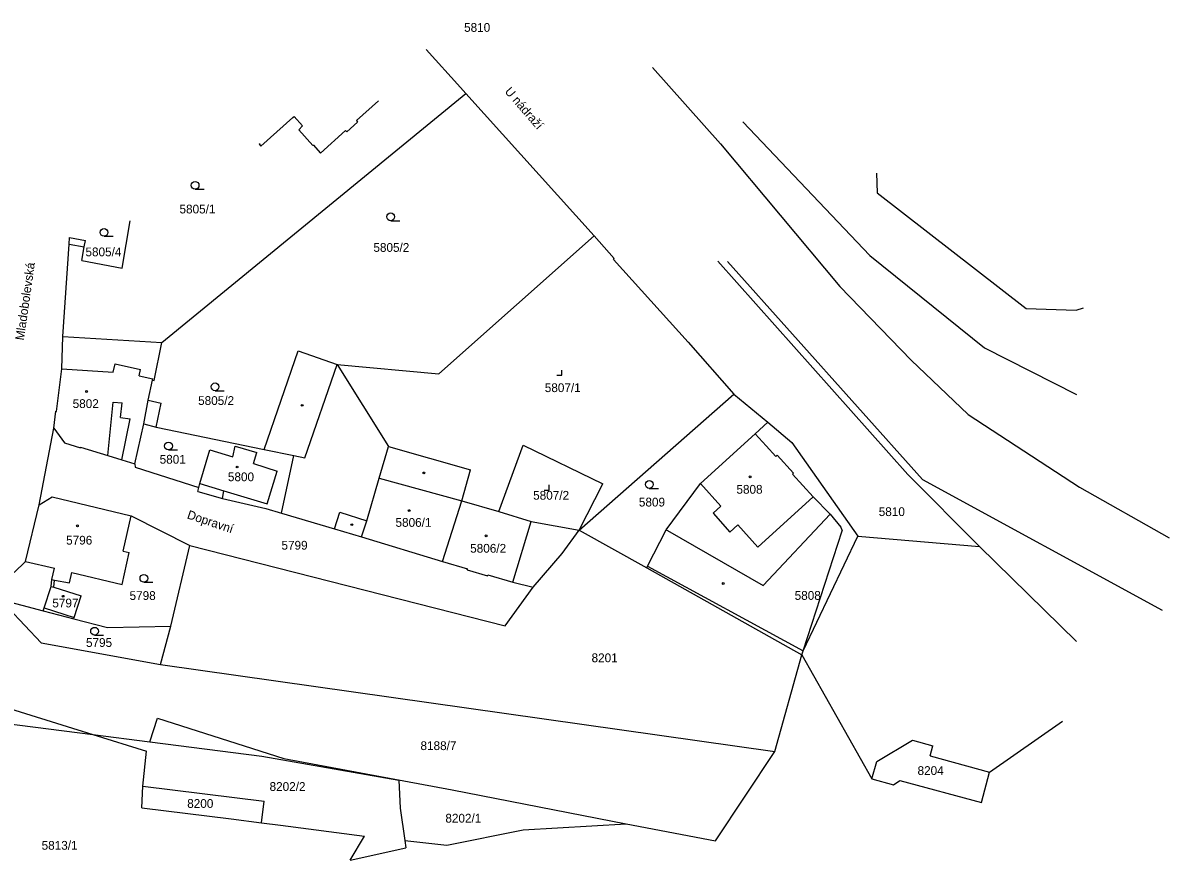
# Model space of a CAD drawing. Extents: x -717507 to -715515, y -957700 to -954941.
# Drawn here: x -715773.2 to -715551.5, y -955101.9 to -954940.9 of the extents above; entities that cross this region are included whole.
import ezdxf

# ---------------------------------------------------------------- set-up
doc = ezdxf.new("R2010")
doc.units = 0
for name, color, linetype in [('Hranice parcel', 7, 'Continuous'), ('Parcelní čísla', 7, 'Continuous'), ('Pop  PČ popisy', 7, 'Continuous'), ('Vnitřní kresba', 7, 'Continuous'), ('Značky budov', 7, 'Continuous'), ('Značky kultur', 7, 'Continuous')]:
    doc.layers.add(name, color=color, linetype=linetype)

msp = doc.modelspace()

# ---------------------------------------------------------------- linework, layer by layer
at = {"layer": 'Hranice parcel'}
for points in [[(-715695.18, -954946.06), (-715688.55, -954953.42)], [(-715651.42, -954949.56), (-715638.23, -954964.35)], [(-715688.55, -954953.42), (-715687.49, -954954.6)], [(-715746.28, -955002.75), (-715687.49, -954954.6)], [(-715708.67, -954959.84), (-715704.37, -954955.99)], [(-715687.49, -954954.6), (-715662.66, -954982.12)], [(-715727.15, -954964.76), (-715720.95, -954959.22)], [(-715720.95, -954959.22), (-715720.72, -954959.01)], [(-715720.72, -954959.01), (-715719.08, -954960.85)], [(-715710.55, -954962), (-715708.44, -954960.11)], [(-715708.67, -954959.84), (-715708.44, -954960.11)], [(-715633.96, -954960.07), (-715609.35, -954985.91)], [(-715719.82, -954961.59), (-715719.08, -954960.85)], [(-715719.82, -954961.59), (-715717.12, -954964.65)], [(-715715.65, -954966.1), (-715710.79, -954961.74)], [(-715710.79, -954961.74), (-715710.55, -954962)], [(-715727.46, -954964.41), (-715727.31, -954964.28)], [(-715727.46, -954964.41), (-715727.15, -954964.76)], [(-715717.12, -954964.65), (-715717.01, -954964.55)], [(-715717.01, -954964.55), (-715715.65, -954966.1)], [(-715638.23, -954964.35), (-715615.16, -954991.91)], [(-715608.08, -954970), (-715607.94, -954973.8)], [(-715607.94, -954973.8), (-715579.15, -954996.19)], [(-715754.01, -954988.4), (-715752.42, -954979.21)], [(-715764.23, -954983.73), (-715764.14, -954982.46)], [(-715764.14, -954982.46), (-715761.09, -954983.03)], [(-715692.71, -955008.8), (-715662.66, -954982.12)], [(-715662.66, -954982.12), (-715658.79, -954986.51)], [(-715765.46, -955001.59), (-715764.23, -954983.73)], [(-715764.23, -954983.73), (-715761.33, -954984.27)], [(-715761.81, -954986.87), (-715761.33, -954984.27)], [(-715761.81, -954986.87), (-715754.01, -954988.4)], [(-715658.94, -954986.68), (-715658.79, -954986.51)], [(-715658.94, -954986.68), (-715644.51, -955002.69)], [(-715638.8, -954987), (-715602, -955028.3)], [(-715636.93, -954987.11), (-715599.17, -955029.27)], [(-715609.35, -954985.91), (-715587.16, -955003.81)], [(-715615.16, -954991.91), (-715601.39, -955006.15)], [(-715579.15, -954996.19), (-715569.45, -954996.5)], [(-715569.45, -954996.5), (-715568.03, -954996.04)], [(-715765.67, -955007.85), (-715765.46, -955001.59)], [(-715765.46, -955001.59), (-715746.28, -955002.75)], [(-715747.81, -955010.09), (-715746.28, -955002.75)], [(-715726.53, -955023.47), (-715719.91, -955004.38)], [(-715719.91, -955004.38), (-715712.38, -955006.99)], [(-715644.51, -955002.69), (-715635.66, -955012.72)], [(-715587.16, -955003.81), (-715569.37, -955012.8)], [(-715712.38, -955006.99), (-715692.71, -955008.8)], [(-715712.38, -955006.99), (-715702.48, -955022.9)], [(-715601.39, -955006.15), (-715590.37, -955016.71)], [(-715766.67, -955016.08), (-715765.67, -955007.85)], [(-715748.97, -955013.91), (-715748.09, -955010.03)], [(-715748.09, -955010.03), (-715747.81, -955010.09)], [(-715665.6, -955039.04), (-715635.66, -955012.72)], [(-715635.66, -955012.72), (-715629.09, -955018.19)], [(-715749.79, -955018.5), (-715748.97, -955013.91)], [(-715767.18, -955019.31), (-715766.78, -955016.07)], [(-715766.78, -955016.07), (-715766.67, -955016.08)], [(-715631.54, -955020.41), (-715629.09, -955018.19)], [(-715629.09, -955018.19), (-715624.43, -955022.07)], [(-715590.37, -955016.71), (-715568.8, -955030.77)], [(-715770.02, -955034.13), (-715767.18, -955019.31)], [(-715767.18, -955019.31), (-715765.15, -955022.14)], [(-715751.51, -955026.24), (-715749.79, -955018.5)], [(-715749.79, -955018.5), (-715747.4, -955019.14)], [(-715747.4, -955019.14), (-715726.53, -955023.47)], [(-715642.15, -955030.02), (-715631.54, -955020.41)], [(-715765.15, -955022.14), (-715762.06, -955023.1)], [(-715681.14, -955035.47), (-715676.44, -955022.6)], [(-715676.44, -955022.6), (-715661.01, -955030.12)], [(-715624.43, -955022.07), (-715611.7, -955040.21)], [(-715762.06, -955023.1), (-715762.03, -955023)], [(-715762.03, -955023), (-715756.74, -955024.63)], [(-715756.74, -955024.63), (-715754.03, -955025.47)], [(-715738.97, -955030.01), (-715737, -955023.54)], [(-715737, -955023.54), (-715732.6, -955024.88)], [(-715732.6, -955024.88), (-715732.15, -955022.83)], [(-715732.15, -955022.83), (-715727.91, -955024.01)], [(-715728.59, -955026.18), (-715727.91, -955024.01)], [(-715726.53, -955023.47), (-715720.77, -955024.62)], [(-715723.18, -955035.74), (-715720.77, -955024.62)], [(-715702.48, -955022.9), (-715686.59, -955027.39)], [(-715754.03, -955025.47), (-715751.51, -955026.24)], [(-715751.51, -955026.24), (-715751.49, -955026.85)], [(-715751.49, -955026.85), (-715739.17, -955030.8)], [(-715728.59, -955026.18), (-715723.98, -955027.62)], [(-715725.95, -955033.99), (-715723.98, -955027.62)], [(-715688.28, -955033.37), (-715686.59, -955027.39)], [(-715602, -955028.3), (-715588.15, -955042.25)], [(-715599.17, -955029.27), (-715552.82, -955054.51)], [(-715739.37, -955031.59), (-715739.17, -955030.8)], [(-715739.17, -955030.8), (-715738.97, -955030.01)], [(-715734.56, -955032.92), (-715734.29, -955031.44)], [(-715734.29, -955031.44), (-715725.95, -955033.99)], [(-715665.6, -955039.04), (-715661.01, -955030.12)], [(-715648.77, -955038.99), (-715642.15, -955030.02)], [(-715568.8, -955030.77), (-715551.49, -955040.56)], [(-715770.02, -955034.13), (-715767.55, -955032.63)], [(-715767.55, -955032.63), (-715752.27, -955036.3)], [(-715739.37, -955031.59), (-715734.56, -955032.92)], [(-715734.56, -955032.92), (-715726.22, -955034.87)], [(-715692.05, -955045.09), (-715688.28, -955033.37)], [(-715688.28, -955033.37), (-715681.14, -955035.47)], [(-715772.65, -955045.12), (-715770.02, -955034.13)], [(-715726.22, -955034.87), (-715723.18, -955035.74)], [(-715723.18, -955035.74), (-715712.94, -955038.77)], [(-715681.14, -955035.47), (-715674.89, -955037.36)], [(-715753.76, -955043.09), (-715752.27, -955036.3)], [(-715752.27, -955036.3), (-715740.88, -955042.03)], [(-715674.89, -955037.36), (-715665.6, -955039.04)], [(-715712.94, -955038.77), (-715707.66, -955040.36)], [(-715707.66, -955040.36), (-715692.05, -955045.09)], [(-715668.9, -955043.56), (-715665.6, -955039.04)], [(-715665.6, -955039.04), (-715652.52, -955046.36)], [(-715652.35, -955046.04), (-715648.77, -955038.99)], [(-715622.27, -955062.39), (-715611.7, -955040.21)], [(-715611.7, -955040.21), (-715588.15, -955042.25)], [(-715744.57, -955057.63), (-715740.88, -955042.03)], [(-715740.88, -955042.03), (-715679.87, -955057.57)], [(-715588.15, -955042.25), (-715569.4, -955060.6)], [(-715753.97, -955049.56), (-715752.6, -955043.35)], [(-715753.76, -955043.09), (-715752.6, -955043.35)], [(-715674.48, -955050.07), (-715668.9, -955043.56)], [(-715774.89, -955047.27), (-715772.65, -955045.12)], [(-715692.05, -955045.09), (-715687.18, -955046.54)], [(-715687.23, -955046.71), (-715687.18, -955046.54)], [(-715687.23, -955046.71), (-715683.3, -955047.88)], [(-715652.52, -955046.36), (-715652.35, -955046.04)], [(-715652.52, -955046.36), (-715622.49, -955063.17)], [(-715767.18, -955050.11), (-715767.05, -955048.72)], [(-715767.05, -955048.72), (-715764.16, -955049.23)], [(-715764.16, -955049.23), (-715763.69, -955047.25)], [(-715763.69, -955047.25), (-715753.97, -955049.56)], [(-715683.3, -955047.88), (-715683.25, -955047.7)], [(-715683.25, -955047.7), (-715678.45, -955049.13)], [(-715678.45, -955049.13), (-715674.48, -955050.07)], [(-715769.05, -955054.1), (-715767.73, -955049.94)], [(-715767.73, -955049.94), (-715767.18, -955050.11)], [(-715767.18, -955050.11), (-715761.93, -955051.78)], [(-715679.87, -955057.57), (-715674.48, -955050.07)], [(-715777.53, -955052.49), (-715769.23, -955054.65)], [(-715763.26, -955055.94), (-715761.93, -955051.78)], [(-715775.97, -955054.15), (-715769.66, -955060.86)], [(-715769.23, -955054.65), (-715769.05, -955054.1)], [(-715769.23, -955054.65), (-715763.33, -955056.19)], [(-715763.33, -955056.19), (-715763.26, -955055.94)], [(-715763.33, -955056.19), (-715756.82, -955057.88)], [(-715756.82, -955057.88), (-715744.57, -955057.63)], [(-715746.57, -955065.07), (-715744.57, -955057.63)], [(-715769.66, -955060.86), (-715746.57, -955065.07)], [(-715622.49, -955063.17), (-715622.27, -955062.39)], [(-715627.77, -955081.89), (-715622.49, -955063.17)], [(-715622.49, -955063.17), (-715608.96, -955087.14)], [(-715746.57, -955065.07), (-715627.77, -955081.89)], [(-715779.8, -955072.31), (-715759.64, -955078.61)], [(-715748.66, -955080.01), (-715747.17, -955075.43)], [(-715747.17, -955075.43), (-715722.72, -955083.25)], [(-715586.21, -955085.86), (-715572.1, -955075.99)], [(-715759.64, -955078.61), (-715749.26, -955081.83)], [(-715759.64, -955078.61), (-715748.66, -955080.01)], [(-715748.66, -955080.01), (-715726.98, -955082.77)], [(-715608.04, -955083.78), (-715601.11, -955079.71)], [(-715601.11, -955079.71), (-715597.17, -955080.76)], [(-715749.97, -955088.61), (-715749.26, -955081.83)], [(-715639.25, -955099.18), (-715627.77, -955081.89)], [(-715597.7, -955082.73), (-715597.17, -955080.76)], [(-715726.98, -955082.77), (-715700.5, -955087.42)], [(-715722.72, -955083.25), (-715690.16, -955089.32)], [(-715608.96, -955087.14), (-715608.04, -955083.78)], [(-715597.7, -955082.73), (-715586.21, -955085.86)], [(-715587.8, -955091.74), (-715586.21, -955085.86)], [(-715750.17, -955092.77), (-715749.97, -955088.61)], [(-715749.97, -955088.61), (-715726.52, -955091.51)], [(-715700.5, -955087.42), (-715700.23, -955092.85)], [(-715608.96, -955087.14), (-715604.79, -955088.31)], [(-715604.79, -955088.31), (-715603.54, -955087.5)], [(-715603.54, -955087.5), (-715587.8, -955091.74)], [(-715690.16, -955089.32), (-715656.48, -955095.85)], [(-715750.17, -955092.77), (-715732.89, -955094.92)], [(-715727, -955095.65), (-715726.52, -955091.51)], [(-715700.23, -955092.85), (-715699.3, -955099.1)], [(-715732.89, -955094.92), (-715727, -955095.65)], [(-715727, -955095.65), (-715723.35, -955096.11)], [(-715723.35, -955096.11), (-715707.14, -955098.25)], [(-715691.16, -955099.97), (-715676.42, -955097.04)], [(-715676.42, -955097.04), (-715656.48, -955095.85)], [(-715656.48, -955095.85), (-715639.25, -955099.18)], [(-715709.87, -955102.92), (-715707.14, -955098.25)], [(-715699.3, -955099.1), (-715691.16, -955099.97)], [(-715699.3, -955099.1), (-715699.09, -955100.5)], [(-715709.87, -955102.92), (-715699.09, -955100.5)]]:
    msp.add_lwpolyline(points, dxfattribs=at)
at = {"layer": 'Vnitřní kresba'}
for points in [[(-715761.33, -954984.27), (-715761.09, -954983.03)], [(-715755.69, -955008.48), (-715755.36, -955006.91)], [(-715755.36, -955006.91), (-715750.44, -955007.96)], [(-715718.67, -955025.04), (-715712.38, -955006.99)], [(-715765.67, -955007.85), (-715755.69, -955008.48)], [(-715750.71, -955009.21), (-715750.44, -955007.96)], [(-715750.71, -955009.21), (-715748.04, -955009.77)], [(-715748.09, -955010.03), (-715748.04, -955009.77)], [(-715756.74, -955024.63), (-715755.72, -955014.31)], [(-715755.72, -955014.31), (-715753.97, -955014.41)], [(-715754.31, -955017.25), (-715753.97, -955014.41)], [(-715748.97, -955013.91), (-715746.41, -955014.46)], [(-715747.4, -955019.14), (-715746.41, -955014.46)], [(-715754.31, -955017.25), (-715752.44, -955017.49)], [(-715754.03, -955025.47), (-715752.44, -955017.49)], [(-715631.54, -955020.41), (-715629.42, -955022.74)], [(-715720.77, -955024.62), (-715718.67, -955025.04)], [(-715704.25, -955028.99), (-715702.48, -955022.9)], [(-715629.42, -955022.74), (-715627.52, -955024.78)], [(-715627.52, -955024.78), (-715627.3, -955024.58)], [(-715627.3, -955024.58), (-715624.12, -955028.03)], [(-715706.67, -955037.27), (-715704.25, -955028.99)], [(-715704.25, -955028.99), (-715688.28, -955033.37)], [(-715624.34, -955028.24), (-715624.12, -955028.03)], [(-715624.34, -955028.24), (-715620.33, -955032.6)], [(-715738.97, -955030.01), (-715734.29, -955031.44)], [(-715642.15, -955030.02), (-715638.2, -955034.4)], [(-715631.03, -955042.34), (-715620.33, -955032.6)], [(-715620.33, -955032.6), (-715617.07, -955035.98)], [(-715712.94, -955038.77), (-715711.9, -955035.59)], [(-715711.9, -955035.59), (-715706.67, -955037.27)], [(-715639.7, -955035.76), (-715638.2, -955034.4)], [(-715639.7, -955035.76), (-715636.42, -955039.42)], [(-715707.66, -955040.36), (-715706.67, -955037.27)], [(-715678.45, -955049.13), (-715674.89, -955037.36)], [(-715636.42, -955039.42), (-715634.9, -955038.05)], [(-715634.9, -955038.05), (-715631.03, -955042.34)], [(-715630.01, -955049.74), (-715617.07, -955035.98)], [(-715617.07, -955035.98), (-715614.99, -955038.49)], [(-715648.77, -955038.99), (-715648.52, -955039.14)], [(-715648.52, -955039.14), (-715630.01, -955049.74)], [(-715622.27, -955062.39), (-715614.75, -955039.22)], [(-715614.99, -955038.49), (-715614.75, -955039.22)], [(-715772.65, -955045.12), (-715767.09, -955046.44)], [(-715767.61, -955048.62), (-715767.09, -955046.44)], [(-715652.35, -955046.04), (-715622.27, -955062.39)], [(-715767.73, -955049.94), (-715767.61, -955048.62)], [(-715767.61, -955048.62), (-715767.05, -955048.72)], [(-715769.05, -955054.1), (-715763.26, -955055.94)], [(-715776.78, -955076.42), (-715759.64, -955078.61)]]:
    msp.add_lwpolyline(points, dxfattribs=at)
at = {"layer": 'Značky budov'}
for centre in [(-715760.86, -955012.24), (-715719.17, -955014.91), (-715731.76, -955026.84), (-715695.64, -955027.99), (-715632.54, -955028.75), (-715698.47, -955035.28), (-715762.64, -955038.21), (-715709.57, -955037.99), (-715683.6, -955040.16), (-715637.72, -955049.37), (-715765.41, -955051.85)]:
    msp.add_circle(centre, 0.175, dxfattribs=at)
at = {"layer": 'Značky kultur'}
for points in [[(-715739.87, -954973.09), (-715738.12, -954973.09)], [(-715702.04, -954979.19), (-715700.29, -954979.19)], [(-715757.49, -954982.21), (-715755.74, -954982.21)], [(-715669.93, -955009.09), (-715668.93, -955009.09), (-715668.93, -955008.09)], [(-715736.01, -955012.08), (-715734.26, -955012.08)], [(-715745.02, -955023.54), (-715743.27, -955023.54)], [(-715672.39, -955031.3), (-715671.39, -955031.3), (-715671.39, -955030.3)], [(-715652.02, -955030.97), (-715650.27, -955030.97)], [(-715749.78, -955049.14), (-715748.03, -955049.14)], [(-715759.32, -955059.36), (-715757.57, -955059.36)]]:
    msp.add_lwpolyline(points, dxfattribs=at)
for centre in [(-715739.87, -954972.34), (-715702.04, -954978.44), (-715757.49, -954981.46), (-715736.01, -955011.33), (-715745.02, -955022.79), (-715652.02, -955030.22), (-715749.78, -955048.39), (-715759.32, -955058.61)]:
    msp.add_circle(centre, 0.75, dxfattribs=at)

# ---------------------------------------------------------------- texts
at = {"layer": 'Parcelní čísla'}
for s, p in [('5810', (-715687.85, -954942.66)), ('5805/1', (-715742.89, -954977.79)), ('5805/4', (-715761.08, -954986.08)), ('5805/2', (-715705.39, -954985.22)), ('5807/1', (-715672.24, -955012.35)), ('5802', (-715763.56, -955015.43)), ('5805/2', (-715739.29, -955014.84)), ('5801', (-715746.73, -955026.2)), ('5800', (-715733.53, -955029.59)), ('5807/2', (-715674.49, -955033.17)), ('5808', (-715635.17, -955032.01)), ('5809', (-715654.04, -955034.48)), ('5810', (-715607.65, -955036.33)), ('5806/1', (-715701.11, -955038.41)), ('5796', (-715764.82, -955041.85)), ('5799', (-715723.17, -955042.83)), ('5806/2', (-715686.67, -955043.42)), ('5798', (-715752.55, -955052.56)), ('5808', (-715623.91, -955052.54)), ('5797', (-715767.49, -955054)), ('5795', (-715760.98, -955061.65)), ('8201', (-715663.19, -955064.6)), ('8188/7', (-715696.28, -955081.6)), ('8204', (-715600.14, -955086.42)), ('8202/2', (-715725.47, -955089.5)), ('8200', (-715741.4, -955092.78)), ('8202/1', (-715691.47, -955095.63)), ('5813/1', (-715769.56, -955100.88))]:
    msp.add_text(s, height=1.7, dxfattribs=at).set_placement(p)
at = {"layer": 'Pop  PČ popisy'}
for s, rotation, p in [('U nádraží', 310.9025, (-715680.09, -954954.26)), ('Mladobolevská', 81.9007, (-715772.99, -955002.42)), ('Dopravní', 341.5027, (-715741.55, -955036.75))]:
    msp.add_text(s, height=1.7, rotation=rotation, dxfattribs=at).set_placement(p)

doc.saveas('drawing.dxf')
